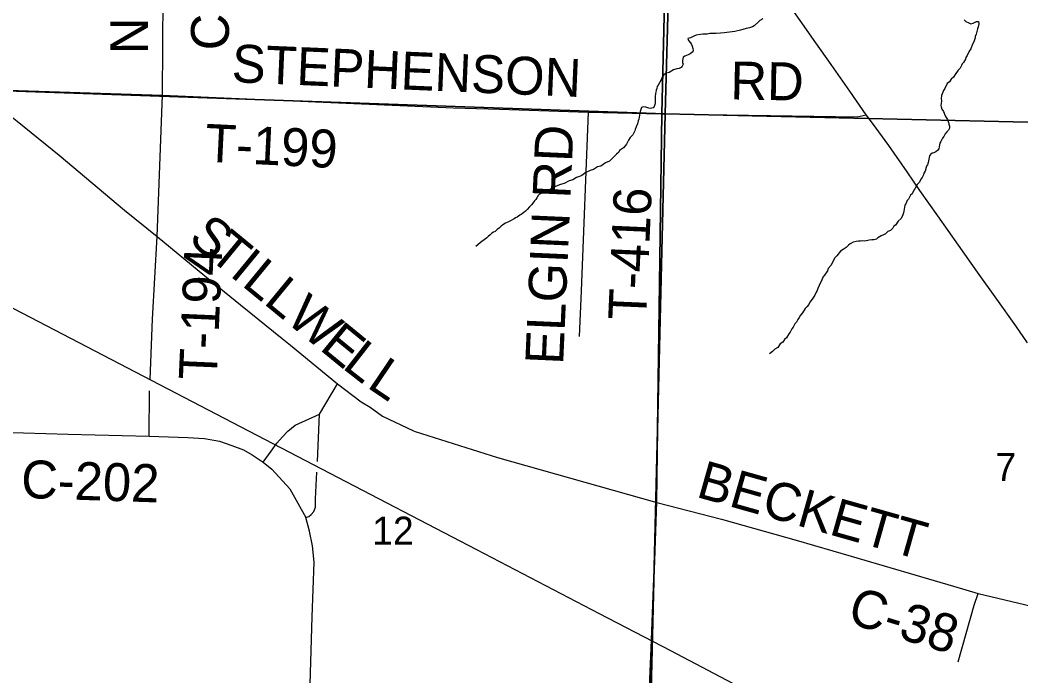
# Model space of a CAD drawing. Extents: x 0 to 34, y 0 to 22.
# Drawn here: x 5.004 to 6.504, y 15.821 to 16.804 of the extents above; entities that cross this region are included whole.
import ezdxf

# ---------------------------------------------------------------- set-up
doc = ezdxf.new("R2010")
doc.units = 0
for name, color, linetype in [('Default', 7, 'Continuous'), ('GM_X_County_Road', 7, 'Continuous'), ('GM_X_County_Road_Text', 7, 'Continuous'), ('GM_X_Minor_River', 7, 'Continuous'), ('GM_X_Rail_Line', 7, 'Continuous'), ('GM_X_Section', 7, 'Continuous'), ('GM_X_Section_Text', 7, 'Continuous'), ('GM_X_Township_Road', 7, 'Continuous'), ('GM_X_Township_Road_Text', 7, 'Continuous'), ('GM_X_US_Route', 7, 'Continuous')]:
    doc.layers.add(name, color=color, linetype=linetype)

msp = doc.modelspace()

# ---------------------------------------------------------------- linework, layer by layer
at = {"layer": 'Default'}
msp.add_lwpolyline([(2.1, 14.1), (5.898, 14.1), (5.9162, 14.6505), (5.9251, 14.9951), (5.9419, 15.65), (5.9423, 15.6675), (5.945, 15.7379), (5.9475, 15.8049), (5.9496, 15.8622), (5.9546, 15.9939), (5.9579, 16.0817), (5.9658, 16.6637), (5.9756, 17.0812), (5.9796, 17.2537), (5.9888, 17.6433), (5.9893, 17.6676), (5.5532, 17.6849), (5.4195, 17.6873), (5.3125, 17.691), (5.2737, 17.6923), (5.2207, 17.6942), (5.1253, 17.6972), (5.0396, 17.6997), (4.98, 17.7015)], dxfattribs=at)
msp.add_lwpolyline([(5.898, 14.1), (8.9, 14.1), (8.9, 17.6104), (8.0065, 17.6245), (7.0308, 17.6406), (6.9889, 17.643), (5.9893, 17.6676), (5.9888, 17.6433), (5.9796, 17.2537), (5.9756, 17.0812), (5.9658, 16.6637), (5.9579, 16.0817), (5.9546, 15.9939), (5.9496, 15.8622), (5.9475, 15.8049), (5.945, 15.7379), (5.9423, 15.6675), (5.9419, 15.65), (5.9251, 14.9951), (5.9162, 14.6505)], close=True, dxfattribs=at)
at = {"layer": 'GM_X_County_Road'}
for points in [[(5.2098, 16.4792), (5.218, 16.6912), (5.2186, 16.8394), (5.2183, 16.888), (5.2211, 16.9137), (5.2276, 16.9358), (5.2397, 16.9731), (5.2493, 16.9947), (5.2573, 17.0071), (5.2626, 17.0139), (5.2715, 17.0198), (5.2878, 17.0229), (5.2916, 17.0379), (5.2945, 17.1001), (5.297, 17.1864), (5.3127, 17.6904)], [(3.4456, 17.5672), (3.4931, 17.5407), (3.5546, 17.5077), (3.6491, 17.4574), (3.7489, 17.4049), (3.8278, 17.3631), (4.0032, 17.2687), (4.1749, 17.1732), (4.3746, 17.0628), (4.4408, 17.0257), (4.6086, 16.9333), (4.7096, 16.8784), (4.747, 16.8517), (4.7876, 16.8185), (4.9398, 16.7), (5, 16.6522), (5.063, 16.6012), (5.161, 16.519), (5.2098, 16.4792), (5.2812, 16.4203), (5.3347, 16.377), (5.3972, 16.3264)], [(5.3972, 16.3264), (5.4093, 16.3166), (5.4801, 16.2585), (5.5153, 16.2317), (5.529, 16.2235), (5.5474, 16.2101), (5.5936, 16.1885)], [(5.3687, 16.1413), (5.3803, 16.1577), (5.3892, 16.1697), (5.3977, 16.1794), (5.4054, 16.188), (5.4167, 16.197), (5.4529, 16.2134), (5.4801, 16.2585)], [(4.9423, 16.1873), (5.0762, 16.1832), (5.1978, 16.1803)], [(5.1978, 16.1803), (5.2555, 16.1785), (5.2806, 16.1769), (5.3031, 16.1726), (5.3218, 16.1665), (5.339, 16.1599), (5.3523, 16.1523), (5.3687, 16.1413)], [(5.5936, 16.1885), (5.5965, 16.1871), (5.7196, 16.1483), (5.9581, 16.0811)], [(5.9581, 16.0811), (6.0552, 16.0559), (6.167, 16.0244), (6.2495, 16.0005), (6.4026, 15.9558), (6.4395, 15.9448), (6.5195, 15.9258), (6.5736, 15.918), (6.6861, 15.9042), (6.7323, 15.8976)]]:
    msp.add_lwpolyline(points, dxfattribs=at)
at = {"layer": 'GM_X_Minor_River'}
for points in [[(6.1169, 16.8053), (6.1127, 16.8027), (6.11, 16.8001), (6.1041, 16.7949), (6.1018, 16.7935), (6.0972, 16.7917), (6.0922, 16.7907), (6.0838, 16.7886), (6.075, 16.7865), (6.0674, 16.7856), (6.0594, 16.7843), (6.0537, 16.784), (6.0472, 16.7834), (6.0423, 16.7836), (6.0377, 16.7833), (6.0339, 16.7826), (6.0301, 16.7823), (6.027, 16.7824), (6.0236, 16.7817), (6.0171, 16.7808), (6.0136, 16.7793), (6.0086, 16.7768), (6.0048, 16.7758), (6.0059, 16.7727), (6.0088, 16.7692), (6.0103, 16.7669)], [(6.4189, 16.8038), (6.4214, 16.8011), (6.4256, 16.7991), (6.4286, 16.7979), (6.432, 16.7989), (6.4344, 16.8), (6.437, 16.8011), (6.4401, 16.8014), (6.4408, 16.798), (6.4395, 16.7931), (6.4387, 16.7904), (6.4366, 16.7825), (6.4354, 16.7791), (6.435, 16.7768), (6.4333, 16.7708), (6.4313, 16.7674), (6.4285, 16.7603), (6.4261, 16.7569), (6.4233, 16.7502), (6.421, 16.7472), (6.4205, 16.7449), (6.4178, 16.74), (6.4158, 16.7378), (6.4146, 16.7352), (6.4126, 16.7314), (6.4099, 16.7285), (6.4052, 16.7221), (6.4028, 16.718), (6.3993, 16.715), (6.3965, 16.7109), (6.3934, 16.7084), (6.3899, 16.7012), (6.3875, 16.6982), (6.3847, 16.6903), (6.3842, 16.6854), (6.3845, 16.6827), (6.3844, 16.6786), (6.3839, 16.6755), (6.3843, 16.6733), (6.385, 16.6702), (6.3875, 16.6663), (6.3904, 16.6602), (6.3919, 16.6575), (6.3937, 16.6548), (6.3951, 16.6502), (6.3958, 16.6475), (6.3965, 16.6445), (6.3965, 16.6418), (6.3953, 16.6388), (6.3929, 16.6362), (6.3902, 16.6332), (6.3882, 16.6291), (6.3862, 16.6265), (6.3838, 16.6216), (6.3822, 16.619), (6.3814, 16.6137), (6.3805, 16.6107), (6.3786, 16.6081), (6.3762, 16.6062), (6.3732, 16.6044), (6.3709, 16.6041), (6.3685, 16.6022), (6.367, 16.6), (6.3653, 16.5928), (6.3648, 16.5902), (6.3636, 16.5868), (6.3624, 16.5845), (6.3604, 16.577), (6.3584, 16.574), (6.358, 16.5717), (6.356, 16.5676), (6.354, 16.5654), (6.3516, 16.5609), (6.3489, 16.5579), (6.3449, 16.5508), (6.3433, 16.5485), (6.3409, 16.5433), (6.3382, 16.5411), (6.3351, 16.5354), (6.3331, 16.5332), (6.3311, 16.5283), (6.3299, 16.5261), (6.329, 16.5204), (6.3282, 16.5174), (6.3277, 16.5147), (6.3269, 16.5117), (6.3241, 16.5061), (6.3198, 16.5024), (6.3159, 16.4964), (6.3132, 16.4946), (6.3116, 16.492), (6.3081, 16.4882), (6.3043, 16.4868), (6.3008, 16.4831)], [(6.0103, 16.7669), (6.011, 16.7642), (6.0124, 16.7607), (6.0128, 16.7581), (6.012, 16.7558), (6.0081, 16.7529), (6.0054, 16.7514), (6.0027, 16.7504), (6.0004, 16.7493), (5.9977, 16.7478), (5.9968, 16.7429), (5.9967, 16.7399), (5.9975, 16.7376), (5.9962, 16.7346), (5.9947, 16.7323), (5.9916, 16.7309), (5.9882, 16.7302), (5.9832, 16.7288), (5.9766, 16.7252), (5.9724, 16.7238), (5.9686, 16.7216), (5.967, 16.719), (5.9646, 16.7141), (5.9602, 16.7062), (5.959, 16.704), (5.9582, 16.7009), (5.9574, 16.6987), (5.9566, 16.6957), (5.9561, 16.6934), (5.9556, 16.6885), (5.9556, 16.6862), (5.9559, 16.6839), (5.9558, 16.6793), (5.9554, 16.6771), (5.9545, 16.6741), (5.953, 16.6718), (5.9488, 16.6708), (5.9461, 16.6716), (5.9416, 16.6732), (5.9378, 16.6733), (5.9355, 16.6723), (5.9334, 16.6666), (5.933, 16.664), (5.9322, 16.6613), (5.9313, 16.6549), (5.9305, 16.6526), (5.9292, 16.6481), (5.9272, 16.6436), (5.9256, 16.6398), (5.9252, 16.6376), (5.9224, 16.6316), (5.9185, 16.6275), (5.9157, 16.6237), (5.9145, 16.6204), (5.9129, 16.6177), (5.9082, 16.6122), (5.9024, 16.6081), (5.9016, 16.6055), (5.8977, 16.6025), (5.8934, 16.5981), (5.8907, 16.5959), (5.8876, 16.5922), (5.8815, 16.5896), (5.8745, 16.5849), (5.8695, 16.5839), (5.8634, 16.5798), (5.8584, 16.5781), (5.8518, 16.5752), (5.848, 16.5722), (5.8457, 16.5708), (5.8422, 16.5694), (5.838, 16.5676), (5.8326, 16.5643), (5.8268, 16.5625), (5.8195, 16.5585), (5.8138, 16.5571), (5.8099, 16.5557), (5.8053, 16.5536), (5.8023, 16.5525), (5.798, 16.5492), (5.793, 16.5478), (5.7865, 16.5441), (5.7826, 16.5427), (5.7807, 16.5405), (5.7783, 16.5371), (5.7771, 16.5345), (5.7748, 16.5327), (5.7724, 16.5293), (5.7705, 16.5267), (5.7677, 16.5237), (5.7642, 16.5196), (5.7615, 16.5174), (5.7592, 16.5152), (5.7553, 16.5123), (5.753, 16.5112), (5.7491, 16.5082), (5.7468, 16.5071), (5.7445, 16.5057), (5.7391, 16.5028), (5.736, 16.5013), (5.7318, 16.4992)], [(5.7318, 16.4992), (5.7276, 16.4966), (5.7252, 16.4948), (5.7225, 16.4922), (5.719, 16.4896), (5.7163, 16.4866), (5.7136, 16.4856), (5.7113, 16.4841), (5.7086, 16.4819), (5.7055, 16.4793), (5.7035, 16.4771), (5.6997, 16.4741), (5.6962, 16.4716), (5.6939, 16.4701), (5.69, 16.4668), (5.6873, 16.4646)], [(6.3008, 16.4831), (6.2977, 16.4817), (6.2946, 16.4802), (6.2919, 16.4788), (6.2896, 16.4773), (6.2873, 16.4755), (6.2834, 16.4744), (6.2804, 16.4741), (6.2766, 16.4738), (6.2701, 16.4725), (6.2659, 16.4726), (6.2632, 16.4723), (6.2602, 16.4723), (6.2568, 16.472), (6.2526, 16.4706), (6.2479, 16.4685), (6.2452, 16.4666), (6.2417, 16.4629), (6.2375, 16.46), (6.2332, 16.4574), (6.2281, 16.4503), (6.2242, 16.447), (6.2234, 16.4444), (6.219, 16.4361), (6.2148, 16.4313), (6.2139, 16.4279), (6.2096, 16.4212), (6.2072, 16.4186), (6.2052, 16.4129), (6.2032, 16.4096), (6.2016, 16.4058), (6.1996, 16.4013), (6.1984, 16.3987), (6.1968, 16.396), (6.1948, 16.3915), (6.1909, 16.3855), (6.1877, 16.3811), (6.1858, 16.3777), (6.183, 16.374), (6.1803, 16.3714), (6.1763, 16.365), (6.1736, 16.3613), (6.1716, 16.3579), (6.1696, 16.3549), (6.1673, 16.3512), (6.1649, 16.3486), (6.1625, 16.3437), (6.1606, 16.3411), (6.1582, 16.3362), (6.1558, 16.3336), (6.1526, 16.3276), (6.1495, 16.325), (6.1468, 16.3213), (6.1429, 16.3184), (6.1394, 16.3131), (6.1351, 16.3106), (6.1316, 16.3072), (6.127, 16.3036)]]:
    msp.add_lwpolyline(points, dxfattribs=at)
at = {"layer": 'GM_X_Rail_Line'}
msp.add_lwpolyline([(4.6429, 16.5543), (5.4558, 16.1314), (5.6881, 16.0106), (5.8718, 15.9147), (5.9787, 15.8592), (6.1465, 15.7709), (6.1767, 15.7561), (6.2472, 15.7195), (6.3997, 15.6402), (6.7392, 15.4634), (7.1004, 15.275), (7.4433, 15.0968), (7.4901, 15.0727), (7.5481, 15.0419), (7.6194, 15.0032)], dxfattribs=at)
at = {"layer": 'GM_X_Section'}
for points in [[(4.989, 17.6982), (5.9983, 17.6719), (5.9708, 16.6629), (4.9556, 16.6985)], [(5.9983, 17.6719), (7.0009, 17.6487), (7.0384, 17.6474), (7.0136, 16.6391), (5.9708, 16.6629)], [(4.9556, 16.6985), (5.9708, 16.6629), (5.9463, 15.655), (4.9226, 15.6806)], [(5.9708, 16.6629), (7.0136, 16.6391), (6.9929, 15.633), (5.9463, 15.655)]]:
    msp.add_lwpolyline(points, close=True, dxfattribs=at)
at = {"layer": 'GM_X_Township_Road'}
for p, q in [((4.9398, 16.7), (5.218, 16.6912)), ((5.1978, 16.1803), (5.1984, 16.2481)), ((5.4499, 16.1425), (5.4529, 16.2134))]:
    msp.add_line(p, q, dxfattribs=at)
for points in [[(5.218, 16.6912), (5.6537, 16.6718), (5.7225, 16.67), (5.8555, 16.6656), (5.965, 16.6632)], [(5.8555, 16.6656), (5.8449, 16.3981), (5.8419, 16.3297)], [(5.965, 16.6632), (5.966, 16.6632), (6.2586, 16.6587), (6.2719, 16.6617)], [(5.1992, 16.2654), (5.2027, 16.3556), (5.2098, 16.4792)], [(5.3687, 16.1413), (5.3814, 16.1309), (5.4083, 16.1012), (5.4323, 16.0586)], [(5.4422, 15.9098), (5.4448, 15.9918), (5.4427, 16.0159), (5.4379, 16.0382), (5.4323, 16.0586), (5.4368, 16.0602), (5.4403, 16.0628), (5.4445, 16.0674), (5.447, 16.0738), (5.4472, 16.0864), (5.4489, 16.1265)], [(5.9165, 14.6499), (5.9253, 14.9946), (5.9422, 15.6495), (5.9426, 15.667), (5.9452, 15.7374), (5.9477, 15.8043), (5.9499, 15.8617), (5.9548, 15.9934), (5.9581, 16.0811)], [(6.4095, 15.8422), (6.4335, 15.9274), (6.4395, 15.9448)], [(5.4111, 14.6617), (5.4139, 14.7803), (5.4186, 15.0073), (5.4215, 15.3292), (5.4343, 15.6571), (5.4422, 15.9098)]]:
    msp.add_lwpolyline(points, dxfattribs=at)
at = {"layer": 'GM_X_US_Route'}
msp.add_lwpolyline([(6.5135, 16.32), (6.4959, 16.3456), (6.4677, 16.3853), (6.4388, 16.426), (6.4103, 16.4665), (6.3793, 16.5103), (6.3523, 16.5482), (6.3334, 16.576), (6.3056, 16.6156), (6.2812, 16.6493), (6.2719, 16.6617), (6.2476, 16.6972), (6.2194, 16.737), (6.1963, 16.7696), (6.1731, 16.8029), (6.1498, 16.8356)], dxfattribs=at)

# ---------------------------------------------------------------- texts
at = {"layer": 'GM_X_County_Road_Text'}
for s, height, rotation, p in [('C', 0.0568, 89.9971, (5.3173, 16.7582)), ('N', 0.0568, 90, (5.1962, 16.7524)), ('S', 0.0568, 320.5499, (5.2545, 16.473)), ('T', 0.0568, 320.5451, (5.2841, 16.4487)), ('I', 0.0568, 320.5517, (5.3169, 16.4216)), ('L', 0.0568, 320.549, (5.3349, 16.4068)), ('L', 0.0568, 320.5451, (5.3677, 16.3798)), ('W', 0.0568, 320.552, (5.4005, 16.3528)), ('E', 0.0568, 320.6867, (5.4515, 16.3109)), ('L', 0.0568, 321.9785, (5.4855, 16.2831)), ('L', 0.0568, 325.9284, (5.5224, 16.2544)), ('C-202', 0.05682, 358.0725, (5.0053, 16.0879)), ('BECKETT', 0.05682, 344.238, (6.0155, 16.0898)), ('C-38', 0.05682, 343.2015, (6.2417, 15.9012))]:
    msp.add_text(s, height=height, rotation=rotation, dxfattribs=at).set_placement(p)
at = {"layer": 'GM_X_Section_Text'}
for s, height, p in [('7', 0.0419, (6.4653, 16.113)), ('12', 0.04186, (5.5319, 16.0178))]:
    msp.add_text(s, height=height, rotation=0, dxfattribs=at).set_placement(p)
at = {"layer": 'GM_X_Township_Road_Text'}
for s, rotation, p in [('STEPHENSON', 357.5413, (5.3207, 16.7106)), ('RD', 359.0128, (6.0682, 16.6847)), ('T-199', 357.1941, (5.2804, 16.5914)), ('ELGIN RD', 87.4846, (5.8179, 16.2867)), ('T-416', 87.4736, (5.9421, 16.3533)), ('T-194', 87.4868, (5.2988, 16.2636))]:
    msp.add_text(s, height=0.05682, rotation=rotation, dxfattribs=at).set_placement(p)

doc.saveas('drawing.dxf')
